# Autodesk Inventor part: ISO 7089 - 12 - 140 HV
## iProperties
Created: 2007-05
Part Number: ISO 7089 - 12 - 140 HV
Material: Steel, Mild
Description: Washer
Vendor: Autodesk Inc.
Document SubType Name: Modeling
Standard: ISO 7089
Designer: kurs1
Standards Organization: ISO
Language: en-US
Size Designation: 12 - 140 HV
Categories: <MemberInstance Version="R10.0.0"><Categories><Category DisplayName="Fasteners" InternalName="e4da775c-781d-43d5-af7c-5136215cf5a6" Mnemonic="FSTN"><Category Di
Density: 1 g/cm^3
Author: kurs1
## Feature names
1. Body [Extrusion]
